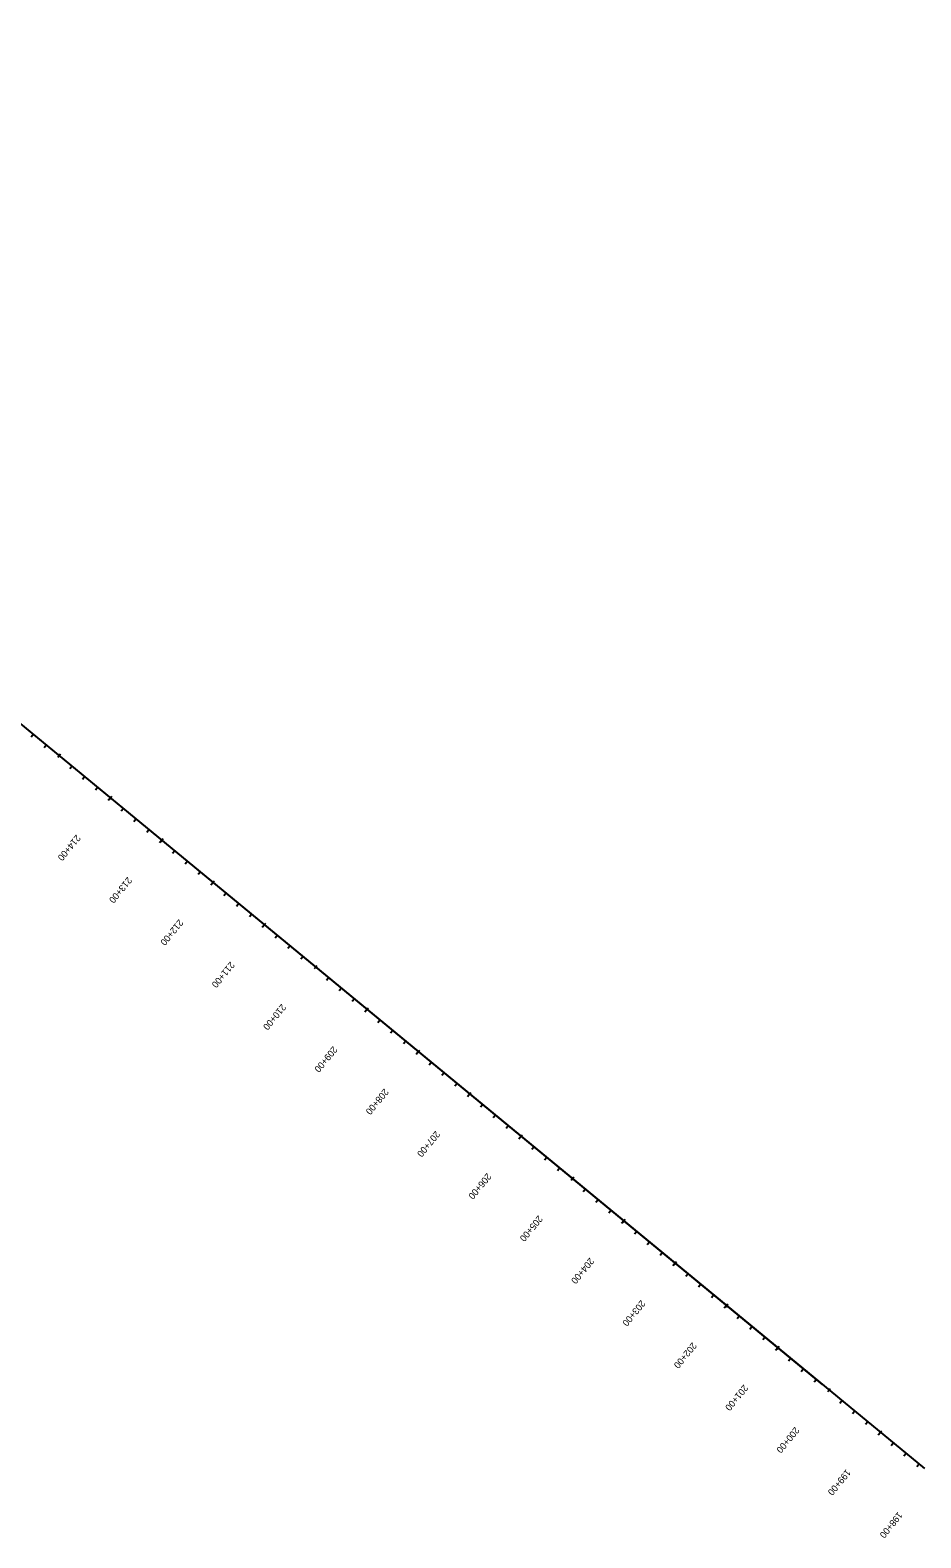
# Model space of a CAD drawing. Extents: x 5226274 to 5237131, y 3641705 to 3648830.
# Drawn here: x 5227622 to 5228961, y 3646462 to 3648728 of the extents above; entities that cross this region are included whole.
import ezdxf

# ---------------------------------------------------------------- set-up
doc = ezdxf.new("R2010")
doc.units = 0
for name, color, linetype in [('Alignment', 7, 'Continuous'), ('TextAlignmentLrg', 7, 'Continuous'), ('TextAlignmentSml', 7, 'Continuous')]:
    doc.layers.add(name, color=color, linetype=linetype)

msp = doc.modelspace()

# ---------------------------------------------------------------- linework, layer by layer
at = {"layer": 'Alignment'}
for p in [(5228813, 3646692.7), (5228966.5, 3646566.3)]:
    msp.add_line(p, (5226341.7, 3648728.2), dxfattribs=at)
at = {"layer": 'TextAlignmentLrg'}
for p, q in [((5227663.3, 3647635.7), (5227667.2, 3647640.4)), ((5227742.5, 3647574.5), (5227739, 3647570.3)), ((5227819.7, 3647510.9), (5227816.2, 3647506.7)), ((5227896.8, 3647447.3), (5227893.4, 3647443.1)), ((5227974, 3647383.8), (5227970.6, 3647379.5)), ((5228049.3, 3647317.8), (5228053.2, 3647322.5)), ((5228128.4, 3647256.6), (5228124.9, 3647252.4)), ((5228205.6, 3647193), (5228202.1, 3647188.8)), ((5228282.8, 3647129.4), (5228279.3, 3647125.2)), ((5228360, 3647065.9), (5228356.5, 3647061.7)), ((5228435.2, 3646999.9), (5228439.1, 3647004.7)), ((5228514.3, 3646938.7), (5228510.9, 3646934.5)), ((5228591.5, 3646875.1), (5228588.1, 3646870.9)), ((5228668.7, 3646811.6), (5228665.2, 3646807.3)), ((5228745.9, 3646748), (5228742.4, 3646743.8)), ((5228821.1, 3646682), (5228825, 3646686.8)), ((5228900.3, 3646620.8), (5228896.8, 3646616.6))]:
    msp.add_line(p, q, dxfattribs=at)
at = {"layer": 'TextAlignmentSml'}
for p, q in [((5227626.7, 3647669.9), (5227623.2, 3647665.6)), ((5227646, 3647654), (5227642.5, 3647649.7)), ((5227663.3, 3647635.7), (5227667.2, 3647640.4)), ((5227684.6, 3647622.2), (5227681.1, 3647618)), ((5227703.9, 3647606.3), (5227700.4, 3647602.1)), ((5227723.2, 3647590.4), (5227719.7, 3647586.2)), ((5227740.5, 3647572.1), (5227744.4, 3647576.8)), ((5227761.8, 3647558.6), (5227758.3, 3647554.4)), ((5227781.1, 3647542.7), (5227777.6, 3647538.5)), ((5227800.4, 3647526.8), (5227796.9, 3647522.6)), ((5227817.7, 3647508.5), (5227821.6, 3647513.3)), ((5227839, 3647495), (5227835.5, 3647490.8)), ((5227858.2, 3647479.1), (5227854.8, 3647474.9)), ((5227877.5, 3647463.2), (5227874.1, 3647459)), ((5227894.9, 3647445), (5227898.8, 3647449.7)), ((5227916.1, 3647431.4), (5227912.7, 3647427.2)), ((5227935.4, 3647415.5), (5227932, 3647411.3)), ((5227954.7, 3647399.6), (5227951.3, 3647395.4)), ((5227972.1, 3647381.4), (5227976, 3647386.1)), ((5227993.3, 3647367.9), (5227989.9, 3647363.6)), ((5228012.6, 3647352), (5228009.2, 3647347.8)), ((5228031.9, 3647336.1), (5228028.4, 3647331.9)), ((5228049.3, 3647317.8), (5228053.2, 3647322.5)), ((5228070.5, 3647304.3), (5228067, 3647300.1)), ((5228089.8, 3647288.4), (5228086.3, 3647284.2)), ((5228109.1, 3647272.5), (5228105.6, 3647268.3)), ((5228126.5, 3647254.2), (5228130.3, 3647259)), ((5228147.7, 3647240.7), (5228144.2, 3647236.5)), ((5228167, 3647224.8), (5228163.5, 3647220.6)), ((5228186.3, 3647208.9), (5228182.8, 3647204.7)), ((5228203.6, 3647190.7), (5228207.5, 3647195.4)), ((5228224.9, 3647177.1), (5228221.4, 3647172.9)), ((5228244.2, 3647161.2), (5228240.7, 3647157)), ((5228263.5, 3647145.3), (5228260, 3647141.1)), ((5228280.8, 3647127.1), (5228284.7, 3647131.8)), ((5228302.1, 3647113.6), (5228298.6, 3647109.3)), ((5228321.4, 3647097.7), (5228317.9, 3647093.4)), ((5228340.7, 3647081.8), (5228337.2, 3647077.5)), ((5228358, 3647063.5), (5228361.9, 3647068.2)), ((5228379.3, 3647050), (5228375.8, 3647045.8)), ((5228398.6, 3647034.1), (5228395.1, 3647029.9)), ((5228417.9, 3647018.2), (5228414.4, 3647014)), ((5228435.2, 3646999.9), (5228439.1, 3647004.7)), ((5228456.5, 3646986.4), (5228453, 3646982.2)), ((5228475.7, 3646970.5), (5228472.3, 3646966.3)), ((5228495, 3646954.6), (5228491.6, 3646950.4)), ((5228512.4, 3646936.4), (5228516.3, 3646941.1)), ((5228533.6, 3646922.8), (5228530.2, 3646918.6)), ((5228552.9, 3646906.9), (5228549.5, 3646902.7)), ((5228572.2, 3646891), (5228568.8, 3646886.8)), ((5228589.6, 3646872.8), (5228593.5, 3646877.5)), ((5228610.8, 3646859.2), (5228607.4, 3646855)), ((5228630.1, 3646843.3), (5228626.7, 3646839.1)), ((5228649.4, 3646827.5), (5228645.9, 3646823.2)), ((5228666.8, 3646809.2), (5228670.7, 3646813.9)), ((5228688, 3646795.7), (5228684.5, 3646791.4)), ((5228707.3, 3646779.8), (5228703.8, 3646775.6)), ((5228726.6, 3646763.9), (5228723.1, 3646759.7)), ((5228744, 3646745.6), (5228747.8, 3646750.3)), ((5228765.2, 3646732.1), (5228761.7, 3646727.9)), ((5228784.5, 3646716.2), (5228781, 3646712)), ((5228803.8, 3646700.3), (5228800.3, 3646696.1)), ((5228821.1, 3646682), (5228825, 3646686.8)), ((5228842.4, 3646668.5), (5228838.9, 3646664.3)), ((5228861.7, 3646652.6), (5228858.2, 3646648.4)), ((5228881, 3646636.7), (5228877.5, 3646632.5)), ((5228898.3, 3646618.5), (5228902.2, 3646623.2)), ((5228919.6, 3646604.9), (5228916.1, 3646600.7)), ((5228938.9, 3646589), (5228935.4, 3646584.8)), ((5228958.2, 3646573.1), (5228954.7, 3646568.9))]:
    msp.add_line(p, q, dxfattribs=at)

# ---------------------------------------------------------------- texts
at = {"layer": 'TextAlignmentLrg'}
for s, p in [('210+00', (5227999.7, 3647265.5)), ('205+00', (5228385.6, 3646947.6)), ('200+00', (5228771.5, 3646629.7))]:
    msp.add_text(s, height=10.02, rotation=230.5226, dxfattribs=at).set_placement(p)
at = {"layer": 'TextAlignmentSml'}
for s, rotation, p in [('214+00', 230.5226, (5227690.9, 3647519.8)), ('213+00', 230.5226, (5227768.1, 3647456.2)), ('212+00', 230.5226, (5227845.3, 3647392.6)), ('211+00', 230.5226, (5227922.5, 3647329)), ('210+00', 230.5226, (5227999.7, 3647265.5)), ('209+00', 230.5226, (5228076.9, 3647201.9)), ('208+00', 230.5226, (5228154, 3647138.3)), ('207+00', 230.5226, (5228231.2, 3647074.7)), ('206+00', 230.5226, (5228308.4, 3647011.2)), ('205+00', 230.5226, (5228385.6, 3646947.6)), ('204+00', 230.5226, (5228462.8, 3646884)), ('203+00', 230.5226, (5228540, 3646820.4)), ('202+00', 230.5226, (5228617.2, 3646756.9)), ('201+00', 230.5226, (5228694.4, 3646693.3)), ('200+00', 230.5226, (5228771.5, 3646629.7)), ('199+00', 230.5226, (5228848.7, 3646566.1)), ('198+00', 231.0675, (5228926.5, 3646502.1))]:
    msp.add_text(s, height=10.02, rotation=rotation, dxfattribs=at).set_placement(p)

doc.saveas('drawing.dxf')
